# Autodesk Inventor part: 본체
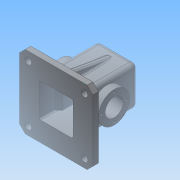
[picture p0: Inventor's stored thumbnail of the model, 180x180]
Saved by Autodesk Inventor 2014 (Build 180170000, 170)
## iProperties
Created: 2016-02
Part Number: 본체
Material: 일반
Document SubType Name: Modeling
Designer: net
Density: 1 g/cm^3
Appearance: 기본값
Mass: 348.017 g
Surface Area: 985.078 cm^2
Volume: 348.017 cm^3
Author: net
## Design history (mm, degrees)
sketch "스케치1"
  geometry: L1 (0, -130)-(-130, -130); L2 (-130, -130)-(-130, 0); L3 (-130, 0)-(0, 0); L4 (0, 0)-(0, -130); 1 further point
  constraints: 8 end point, 2 parallel, 1 coincident, 1 horizontal, 1 perpendicular
  dimensions: "d0" = 130 distance of L1.start L1.end; "d1" = 130 distance of L1.end L2.end
extrude "돌출1" new body sketch "스케치1" distance "d2" = 10; taper "d3" = 0 deg
sketch "스케치2"
  geometry: L1 (130, 130)-(0, 130) reference; L2 (130, 0)-(130, 130) reference; L3 (130, 130)-(0, 130) reference; L4 (0, 130)-(0, 0) reference; L5 (0, 0)-(130, 0) reference; L6 (130, 0)-(130, 130) reference; L7 (65, 130)-(65, 0); L8 (0, 65)-(130, 65); L9 (30, 100)-(100, 100); L10 (100, 100)-(100, 30); L11 (100, 30)-(30, 30); L12 (30, 30)-(30, 100); 1 further point
  constraints: 12 end point, 4 midpoint, 2 parallel, 1 horizontal, 1 perpendicular
  dimensions: "d6" = 70 distance between parallel lines of L12 L10; "d7" = 35 distance between parallel lines of L7 L10; "d8" = 70 distance between parallel lines of L11 L9; "d9" = 35 distance between parallel lines of L8 L9
extrude "돌출2" join sketch "스케치2" distance "d10" = 100; taper "d11" = 0 deg
chamfer "모따기1" distance "d12" = 10; stored, may be unused: second distance "d13" = 2, angle "d14" = 45 deg
sketch "스케치3"
  geometry: L1 (0, 100)-(70, 100) reference; L2 (70, 0)-(70, 100) reference; L3 (0, 0)-(0, 100) reference; L4 (-20, 0)-(90, 0) reference; L5 (90, -10)-(-20, -10) reference; L6 (35, -10)-(35, 45); C1 r 27.5 at (35, 45); 1 further point
  constraints: 2 end point, 1 centre point, 1 coincident, 1 midpoint, 1 perpendicular
  dimensions: "d15" = 55 distance of L6.start L6.end; "d16" = 55 diameter of C1
extrude "돌출3" join sketch "스케치3" distance "d17" = 13; taper "d18" = 0 deg
node "작업 평면1"
sketch "스케치4"
  geometry: L1 (100, 100)-(30, 100) reference; L2 (100, 30)-(100, 100) reference; L3 (30, 30)-(100, 30) reference; L4 (30, 100)-(30, 30) reference; L5 (65, 100)-(65, 30); L6 (30, 65)-(100, 65); C1 r 20 at (65, 65); 1 further point
  constraints: 5 midpoint, 4 end point, 1 centre point
  dimensions: "d19" = 40 diameter of C1
extrude "돌출4" join sketch "스케치4" distance "d20" = 10; taper "d21" = 0 deg
feature "면 기울기1" dims angle "d22" = 10 deg
fillet "모깎기1" dims "d23" = 8
fillet "모깎기2" dims "d24" = 8
fillet "모깎기3" dims "d25" = 3
sketch "스케치5"
  geometry: 1 further point
node "작업 평면2"
sketch "스케치6"
  geometry: L1 (-3, 95)-(57, 95); L2 (57, -20)-(-3, -20); L3 (-8, 50.22)-(-8, 92) reference; L4 (62, 92)-(62, 50.22) reference; L5 (0, 100)-(54, 100) reference; L6 (-21, 17.5)-(-21, 72.5) reference; L7 (75, 17.5)-(75, 72.5) reference; L8 (-21, 45)-(75, 45); L9 (-3, -20)-(-3, 17.5); L10 (-3, 72.5)-(-3, 95); L11 (57, 17.5)-(57, -20); L12 (4, 17.5)-(10.978, 17.5); L13 (-3, 17.5)-(4, 24.5); L14 (50, 65.5)-(50, 24.5); L15 (4, 24.5)-(4, 65.5); L16 (-3, 17.5)-(4, 17.5); L17 (-3, 72.5)-(4, 65.5); L18 (27, 95)-(27, -20); L19 (57, 72.5)-(50, 65.5); L20 (50, 24.5)-(50, 65.5); L21 (57, 17.5)-(50, 24.5); L22 (57, 95)-(57, 72.5); 1 further point
  constraints: 34 end point, 7 parallel, 4 midpoint, 4 symmetric about line, 2 horizontal, 2 perpendicular, 1 point on line
  dimensions: "d29" = 5 distance between parallel lines of L1 L5; "d35" = 7 distance between parallel lines of L15 L10; "d36" = 45 deg angle of L16 L13; "d37" = 135 deg angle of L15 L17; "d39" = 115 distance between parallel lines of L2 L1; "d40" = 60 distance between parallel lines of L11 L9; "d41" = 55 distance of L11.start L19.start; "d42" = 55 distance of L9.end L10.start; "d43" = 5 distance between parallel lines of L10 L3; "d44" = 5 distance between parallel lines of L4 L22
extrude "돌출5" cut sketch "스케치6" stored distance "d45" = 60; taper "d46" = 0 deg
sketch "스케치7"
  geometry: C1 r 27.5 at (0, 0) reference; C2 r 16 at (0, 0); 1 further point
  constraints: 1 centre point, 1 coincident
  dimensions: "d47" = 32 diameter of C2
extrude "돌출6" cut sketch "스케치7" stored distance "d48" = 60; taper "d49" = 0 deg
sketch "스케치8"
  geometry: C1 r 27.5 at (0, 0) reference; C2 r 16 at (0, 0); 1 further point
  constraints: 1 centre point, 1 coincident
  dimensions: "d50" = 32 diameter of C2
extrude "돌출7" cut sketch "스케치8" stored distance "d51" = 60; taper "d52" = 0 deg
sketch "스케치9"
  geometry: L1 (0, 22.5)-(0, -22.5); C1 r 27.5 at (0, 0) reference; A1 r 22.5 centre (0, 0) between (0, 22.5) and (0, -22.5); 3 further points
  constraints: 3 coincident, 2 end point, 2 point on circle, 1 centre point, 1 midpoint, 1 vertical
  dimensions: "d53" = 45 diameter of A1
hole "구멍1" sketch "스케치9" at (0, 22.5) diameter "d54" = 4; stored, may be unused: countersink angle "d58" = 90 deg, drill point angle "d60" = 118 deg; dims "d55" = 6, "d56" = 4, "d57" = 2, "d59" = 10
feature "스레드1" dims "d61" = 8, "d62" = 0
feature "스레드2" dims "d66" = 8, "d67" = 0
sketch "스케치10"
  geometry: L1 (100, 0)-(100, -10) reference; L2 (85, 0)-(85, -10); L3 (70, 92)-(70, 0) reference; L4 (85, 0)-(168.896, 0); L5 (85, 0)-(159.352, 0); L6 (85, 0)-(70, 85.069); L7 (85, 0)-(171.382, 0); L8 (90, 0)-(-20, 0) reference; L9 (65, 72.5)-(65, 95) reference; L10 (70, 85.069)-(70, 0); L11 (85, 0)-(70, 0); 1 further point
  constraints: 14 end point, 3 horizontal, 2 point on line, 1 collinear, 1 parallel, 1 perpendicular
  dimensions: "d71" = 15 distance between parallel lines of L1 L2; "d74" = 100 deg angle of L7 L6
extrude "돌출8" join sketch "스케치10" stored distance "d76" = 10; taper "d77" = 0 deg
fillet "모깎기5" dims "d79" = 3
fillet "모깎기6" dims "d80" = 3
fillet "모깎기7" dims "d81" = 3
sketch "스케치11"
  geometry: L1 (35, -45)-(35, 47) reference; L2 (20, 65)-(-20, 65) reference; 3 further points
  constraints: 1 other
  dimensions: "d83" = 35 distance from line of L1 point (0, 35); "d84" = 30 distance from line of point (0, 35) L2
feature "엠보싱1" sketch "스케치11" dims "d6" = 70, "d7" = 35, "d8" = 70, "d9" = 35, "d85" = 0.5, "d86" = 0
sketch "스케치12"
  geometry: C1 r 20 at (0, 0) reference; C2 r 20 at (0, 0) reference; C3 r 14 at (0, 0); 1 further point
  constraints: 1 centre point, 1 coincident
  dimensions: "d87" = 28 diameter of C3
extrude "돌출9" cut sketch "스케치12" distance "d88" = 4; taper "d89" = 0 deg
sketch "스케치13"
  geometry: C1 r 14 at (0, 0) reference; C2 r 10.5 at (0, 0); 1 further point
  constraints: 1 centre point, 1 coincident
  dimensions: "d90" = 21 diameter of C2
extrude "돌출10" cut sketch "스케치13" stored distance "d91" = 4; taper "d92" = 0 deg
sketch "스케치14"
  geometry: L1 (120, 130)-(10, 130) reference; L2 (0, 120)-(0, 10) reference; L3 (10, 0)-(120, 0) reference; L4 (130, 10)-(130, 120) reference; L5 (65, 130)-(65, 0); L6 (0, 65)-(130, 65); C1 r 6 at (115, 115); C2 r 6 at (15, 115); C3 r 6 at (15, 15); C4 r 6 at (115, 15); 1 further point
  constraints: 4 centre point, 4 end point, 4 midpoint, 2 horizontal alignment, 2 vertical alignment
  dimensions: "d93" = 12 diameter of C1; "d94" = 12 diameter of C2; "d95" = 12 diameter of C3; "d96" = 12 diameter of C4; "d97" = 50 distance from line of L5 C2.centre; "d98" = 100 distance of C2.centre C1.centre; "d99" = 100 distance of C3.centre C2.centre; "d100" = 50 distance from line of L6 C2.centre
extrude "돌출11" cut sketch "스케치14" stored distance "d101" = 4; taper "d102" = 0 deg; dims "d27" = 5, "d80" = 3, "d99" = 100, "d103" = 3, "d107" = 0.5
fillet "모깎기9" dims "d103" = 3
fillet "모깎기10" dims "d104" = 3
fillet "모깎기11" dims "d105" = 0.5
fillet "모깎기12" dims "d106" = 0.5
fillet "모깎기13" dims "d107" = 0.5
fillet "모깎기14" dims "d108" = 0.5
node "솔리드1"
mirror "대칭1"
pattern_circular "원형 패턴1" dims angle "d64" = 360 deg
mirror "대칭2"
pattern_circular "원형 패턴2" dims "d69" = 360 deg
mirror "대칭3"
node "투영된 루프1"
node "투영된 루프2"
other parameters: "d28" = 5, "d31" = 55, "d32" = 27.5, "d38" = 7
